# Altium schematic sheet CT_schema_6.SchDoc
size 403 x 220 mm
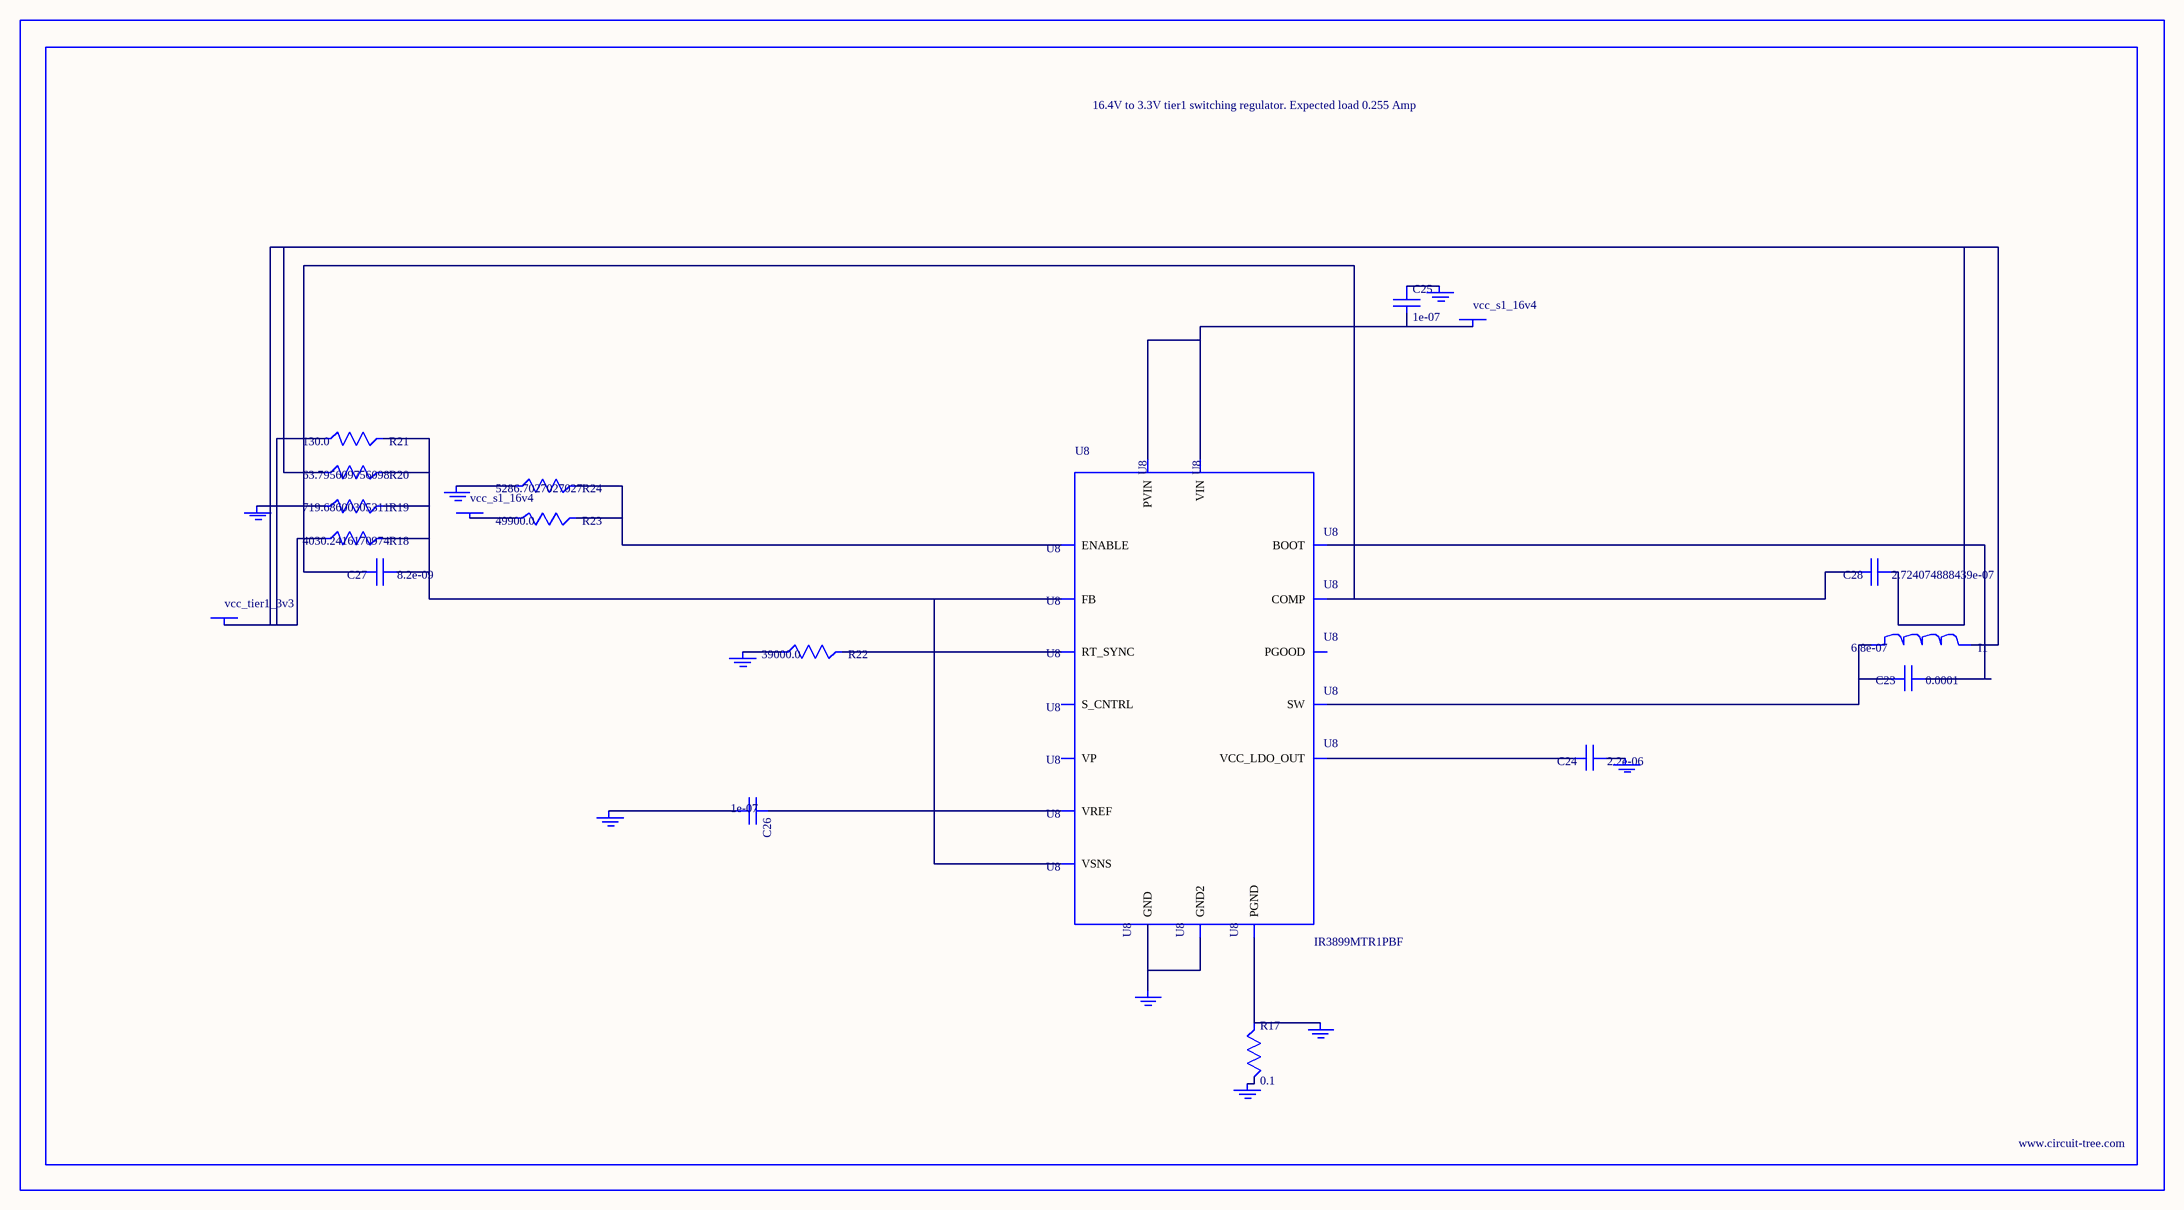
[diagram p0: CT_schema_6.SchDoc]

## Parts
BORDER5  (no value)
C23  0.0001  [C1210]
C24  2.2e-06  [C0603]
C25  1e-07  [C0402]
C26  1e-07  [C0402]
C27  8.2e-09  [C0402]
C28  2.724074888439e-07  [R0603]
GND_INSTANCE_5_0  (no value)
GND_INSTANCE_5_1  (no value)
GND_INSTANCE_5_2  (no value)
GND_INSTANCE_5_3  (no value)
GND_INSTANCE_5_4  (no value)
GND_INSTANCE_5_5  (no value)
GND_INSTANCE_5_6  (no value)
GND_INSTANCE_5_7  (no value)
GND_INSTANCE_5_8  (no value)
I1  6.8e-07  [IND25X25CZ]
POWER_INSTANCE_5_0  vcc_s1_16v4
POWER_INSTANCE_5_1  vcc_s1_16v4
POWER_INSTANCE_5_2  vcc_tier1_3v3
R17  0.1  [R0603]
R18  4030.2416170974  [R0603]
R19  719.68600305311  [R0603]
R20  63.795609756098  [R0603]
R21  130.0  [R0603]
R22  39000.0  [R0603]
R23  49900.0  [R0603]
R24  5286.7027027027  [R0603]
U8  IR3899MTR1PBF  [IR3899MTR1PBF]

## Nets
NetC23_1: C23.1 U8.14(BOOT)
NetC23_2: C23.2 I1.1 U8.12(SW)
NetC24_1: C24.1 GND_INSTANCE_5_4.0(GND)
NetC24_2: C24.2 U8.10(VCC_LDO_OUT)
NetC25_1: C25.1 GND_INSTANCE_5_3.0(GND)
NetC25_2: C25.2 POWER_INSTANCE_5_0.0(PWR) U8.9(VIN) U8.13(PVIN)
NetC26_1: C26.1 U8.2(VREF)
NetC26_2: C26.2 GND_INSTANCE_5_1.0(GND)
NetC27_1: C27.1 R18.2 R19.2 R20.2 R21.2 U8.1(FB) U8.8(VSNS)
NetC27_2: C27.2 C28.2 U8.3(COMP)
NetC28_1: C28.1 I1.2 POWER_INSTANCE_5_2.0(PWR) R18.1 R20.1 R21.1
NetGND_INSTANCE_5_0_0: GND_INSTANCE_5_0.0(GND) R19.1
NetGND_INSTANCE_5_2_0: GND_INSTANCE_5_2.0(GND) R22.1
NetGND_INSTANCE_5_5_0: GND_INSTANCE_5_5.0(GND) R17.2
NetGND_INSTANCE_5_6_0: GND_INSTANCE_5_6.0(GND) R17.1 U8.11(PGND)
NetGND_INSTANCE_5_7_0: GND_INSTANCE_5_7.0(GND) R24.1
NetGND_INSTANCE_5_8_0: GND_INSTANCE_5_8.0(GND) U8.4(GND) U8.17(GND2)
NetPOWER_INSTANCE_5_1_0: POWER_INSTANCE_5_1.0(PWR) R23.1
NetR22_2: R22.2 U8.5(RT_SYNC)
NetR23_2: R23.2 R24.2 U8.15(ENABLE)

Not connected (* = marked no-connect by the designer): U8 6(S_CNTRL) 7(PGOOD) 16(VP)

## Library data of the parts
BORDER5 = BORDER_PAGE5
C23 = GRM32ER61A107ME20L
C24 = C0603C225K8RACTU
C25 C26 = C0402C104K3RACTU
C27 = C0402C822K3RAC
C28 = C28
GND_INSTANCE_5_0-GND_INSTANCE_5_8 = GND
I1 = IHLP2525CZERR68M01
POWER_INSTANCE_5_0-POWER_INSTANCE_5_2 = PWR
R17 = ERJ-3RSFR10V
R18 = R18
R19 = R19
R20 = R20
R21 = RC0603JR-07130RL
R22 = RC0603JR-0739KL
R23 = RC0603FR-0749K9
R24 = R24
